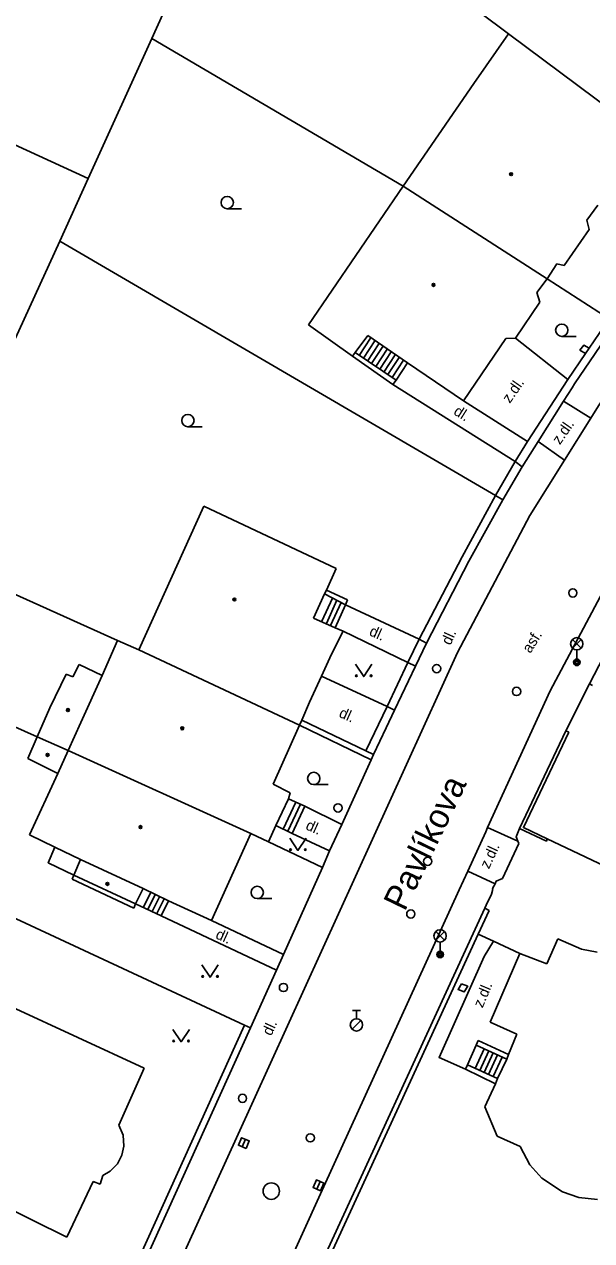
# Model space of a CAD drawing. Extents: x -600309 to -598967, y -1161267 to -1160292.
# Drawn here: x -599972.5 to -599938, y -1160562.7 to -1160488.8 of the extents above; entities that cross this region are included whole.
import ezdxf

# ---------------------------------------------------------------- set-up
doc = ezdxf.new("R2010")
doc.units = 0
for name, color, linetype in [('Level 10', 7, 'Continuous'), ('Level 11', 7, 'Continuous'), ('Level 24', 7, 'Continuous'), ('Level 27', 7, 'Continuous'), ('Level 28', 7, 'Continuous'), ('Level 31', 7, 'Continuous'), ('Level 33', 7, 'Continuous'), ('Level 36', 7, 'Continuous'), ('Level 39', 7, 'Continuous'), ('Level 40', 7, 'Continuous'), ('Level 5', 7, 'Continuous'), ('Level 50', 7, 'Continuous'), ('Level 51', 7, 'Continuous'), ('Level 7', 7, 'Continuous'), ('Level 8', 7, 'Continuous')]:
    doc.layers.add(name, color=color, linetype=linetype)

msp = doc.modelspace()

# ---------------------------------------------------------------- linework, layer by layer
at = {"layer": 'Level 10'}
for points in [[(-599935.03, -1160508.16), (-599937.49, -1160511.84), (-599937.56, -1160511.95), (-599938.03, -1160512.7), (-599939.64, -1160515.26), (-599941.75, -1160518.63), (-599946.15, -1160526.95), (-599959.57, -1160556.4699), (-599964.29, -1160566.81), (-599966.33, -1160571.27), (-599969.39, -1160577.98), (-599972.6, -1160585.01), (-599977.2, -1160595.1)], [(-599971.83, -1160598.12), (-599968.08, -1160589.86), (-599959.85, -1160571.72), (-599958.48, -1160568.71), (-599957.16, -1160565.81), (-599954.26, -1160559.42), (-599946.03, -1160541.39), (-599945.51, -1160540.25), (-599944.42, -1160537.85), (-599944.31, -1160537.6), (-599940.51, -1160529.28), (-599936.62, -1160521.9699), (-599931.52, -1160513.79)]]:
    msp.add_lwpolyline(points, dxfattribs=at)
at = {"layer": 'Level 11'}
for points in [[(-599951.42, -1160507.84), (-599952.11, -1160508.89)], [(-599951.17, -1160508.01), (-599951.86, -1160509.06)], [(-599950.92, -1160508.18), (-599951.61, -1160509.23)], [(-599950.67, -1160508.34), (-599951.36, -1160509.39)], [(-599942.62, -1160507.85), (-599939.43, -1160510.36)], [(-599952.53, -1160508.94), (-599950.07, -1160510.6599)], [(-599952.36, -1160508.7199), (-599949.87, -1160510.4)], [(-599950.42, -1160508.51), (-599951.11, -1160509.56)], [(-599950.17, -1160508.68), (-599950.86, -1160509.73)], [(-599949.93, -1160508.85), (-599950.62, -1160509.9)], [(-599949.68, -1160509.01), (-599950.37, -1160510.06)], [(-599949.43, -1160509.18), (-599950.12, -1160510.23)], [(-599949.87, -1160510.4), (-599949.18, -1160509.35)], [(-599950.07, -1160510.6599), (-599949.87, -1160510.4)], [(-599950.07, -1160510.6599), (-599942.63, -1160515.33)], [(-599941.88, -1160514.12), (-599945.78, -1160511.6599)], [(-599938.03, -1160512.7), (-599939.69, -1160511.68)], [(-599939.64, -1160515.26), (-599941.23, -1160514.13)], [(-599942.63, -1160515.33), (-599943.84, -1160517.4099)], [(-599952.82, -1160523.74), (-599954.1, -1160523.1599)], [(-599954.38, -1160525.04), (-599953.74, -1160523.64)], [(-599952.94, -1160524.05), (-599954.23, -1160523.39)], [(-599954.11, -1160525.18), (-599953.47, -1160523.78)], [(-599953.85, -1160525.31), (-599953.21, -1160523.91)], [(-599952.94, -1160524.05), (-599952.82, -1160523.74)], [(-599953.58, -1160525.45), (-599952.94, -1160524.05)], [(-599948.4699, -1160526.15), (-599952.94, -1160524.05)], [(-599949.15, -1160527.56), (-599953.1, -1160525.65)], [(-599948.4699, -1160526.15), (-599949.15, -1160527.56)], [(-599950.42, -1160530.23), (-599954.4, -1160528.39)], [(-599950.42, -1160530.23), (-599949.96, -1160530.45)], [(-599951.71, -1160532.93), (-599951.24, -1160533.16)], [(-599956.73, -1160537.7), (-599955.97, -1160536.05)], [(-599956.45, -1160537.82), (-599955.69, -1160536.17)], [(-599955.42, -1160536.3), (-599956.42, -1160535.84)], [(-599955.42, -1160536.3), (-599956.18, -1160537.95)], [(-599953.17, -1160537.4), (-599955.42, -1160536.3)], [(-599957.19, -1160537.48), (-599956.18, -1160537.95)], [(-599956.18, -1160537.95), (-599953.92, -1160539.02)], [(-599944.31, -1160537.6), (-599942.47, -1160538.43)], [(-599970.61, -1160538.79), (-599971.02, -1160539.74), (-599969.4699, -1160540.48)], [(-599965.7199, -1160542.23), (-599969.4699, -1160540.48)], [(-599943.86, -1160541.01), (-599945.51, -1160540.25)], [(-599965.23, -1160542.43), (-599964.79, -1160541.53)], [(-599964.96, -1160542.57), (-599964.52, -1160541.67)], [(-599965.7199, -1160542.23), (-599964.15, -1160542.96)], [(-599964.69, -1160542.7), (-599964.25, -1160541.8)], [(-599964.42, -1160542.83), (-599963.98, -1160541.93)], [(-599963.71, -1160542.06), (-599964.15, -1160542.96)], [(-599964.15, -1160542.96), (-599957.14, -1160546.26)], [(-599961.1, -1160543.25), (-599956.7199, -1160545.32)], [(-599945.65, -1160552.29), (-599947.26, -1160551.57), (-599944.52, -1160545.43), (-599943.96, -1160544.5)], [(-599943.96, -1160544.5), (-599944.88, -1160544.08)], [(-599942.35, -1160545.25), (-599943.96, -1160544.5)], [(-599945.01, -1160550.82), (-599944.89, -1160550.55)], [(-599944.89, -1160550.55), (-599943.05, -1160551.4)], [(-599945.53, -1160552.02), (-599945.01, -1160550.82)], [(-599944.51, -1160551.05), (-599945.06, -1160552.24)], [(-599943.15, -1160551.67), (-599945.01, -1160550.82)], [(-599944.24, -1160551.17), (-599944.79, -1160552.36)], [(-599943.97, -1160551.3), (-599944.52, -1160552.49)], [(-599945.65, -1160552.29), (-599945.53, -1160552.02)], [(-599945.53, -1160552.02), (-599943.7, -1160552.86)], [(-599943.7, -1160551.42), (-599944.25, -1160552.61)], [(-599943.42, -1160551.55), (-599943.97, -1160552.74)], [(-599945.65, -1160552.29), (-599943.83, -1160553.17)]]:
    msp.add_lwpolyline(points, dxfattribs=at)
at = {"layer": 'Level 24'}
for points in [[(-599938.35, -1160508.77), (-599938.7, -1160508.57), (-599938.47, -1160508.27), (-599938.13, -1160508.44)], [(-599945.89, -1160547.1), (-599946.1, -1160547.45), (-599945.73, -1160547.59), (-599945.52, -1160547.24), (-599945.89, -1160547.1)]]:
    msp.add_lwpolyline(points, dxfattribs=at)
at = {"layer": 'Level 27'}
for p, q in [((-599959.2265, -1160557.0106), (-599959.0335, -1160556.5494)), ((-599954.6922, -1160559.5781), (-599954.4878, -1160559.1219))]:
    msp.add_line(p, q, dxfattribs=at)
for points in [[(-599958.9958, -1160557.1071), (-599958.8029, -1160556.6458), (-599959.2642, -1160556.4529), (-599959.4571, -1160556.9142)], [(-599954.4641, -1160559.6804), (-599954.2596, -1160559.2241), (-599954.7159, -1160559.0196), (-599954.9204, -1160559.4759)]]:
    msp.add_lwpolyline(points, close=True, dxfattribs=at)
msp.add_circle((-599957.46, -1160559.7), 0.5, dxfattribs=at)
at = {"layer": 'Level 28'}
for p, q in [((-599952.53, -1160548.715), (-599952.03, -1160548.715)), ((-599952.28, -1160549.215), (-599952.28, -1160548.715)), ((-599952.538, -1160549.862), (-599952.008, -1160549.332))]:
    msp.add_line(p, q, dxfattribs=at)
for centre, radius in [((-599939.13, -1160523.33), 0.25), ((-599942.55, -1160529.32), 0.25), ((-599947.95, -1160539.65), 0.25), ((-599948.98, -1160542.85), 0.25), ((-599956.7199, -1160547.32), 0.25), ((-599952.28, -1160549.59), 0.375), ((-599955.09, -1160556.46), 0.25)]:
    msp.add_circle(centre, radius, dxfattribs=at)
at = {"layer": 'Level 31'}
for centre in [(-599947.41, -1160527.93), (-599953.4, -1160536.4), (-599959.21, -1160554.06)]:
    msp.add_circle(centre, 0.25, dxfattribs=at)
at = {"layer": 'Level 33'}
for p, q in [((-599939.155, -1160526.69), (-599938.625, -1160526.16)), ((-599939.155, -1160526.16), (-599938.625, -1160526.69)), ((-599938.89, -1160526.8), (-599938.89, -1160527.55)), ((-599947.465, -1160544.45), (-599946.935, -1160543.92)), ((-599947.465, -1160543.92), (-599946.935, -1160544.45)), ((-599947.2, -1160544.56), (-599947.2, -1160545.31))]:
    msp.add_line(p, q, dxfattribs=at)
for centre, radius in [((-599938.89, -1160526.425), 0.375), ((-599938.89, -1160527.55), 0.2), ((-599938.89, -1160527.55), 0.1445), ((-599938.89, -1160527.55), 0.0876), ((-599947.2, -1160544.185), 0.375), ((-599947.2, -1160545.31), 0.2), ((-599947.2, -1160545.31), 0.1445), ((-599947.2, -1160545.31), 0.0876)]:
    msp.add_circle(centre, radius, dxfattribs=at)
at = {"layer": 'Level 36'}
for p, q in [((-599960.14, -1160499.975), (-599959.265, -1160499.975)), ((-599939.8, -1160507.735), (-599938.925, -1160507.735)), ((-599962.53, -1160513.225), (-599961.655, -1160513.225)), ((-599954.88, -1160534.985), (-599954.005, -1160534.985)), ((-599958.31, -1160541.915), (-599957.435, -1160541.915))]:
    msp.add_line(p, q, dxfattribs=at)
for points in [[(-599952.34, -1160527.67), (-599951.84, -1160528.42), (-599951.34, -1160527.67)], [(-599956.34, -1160538.24), (-599955.84, -1160538.99), (-599955.34, -1160538.24)], [(-599961.68, -1160545.95), (-599961.18, -1160546.7), (-599960.68, -1160545.95)], [(-599963.44, -1160549.87), (-599962.94, -1160550.62), (-599962.44, -1160549.87)]]:
    msp.add_lwpolyline(points, dxfattribs=at)
for centre, radius in [((-599960.1401, -1160499.5999), 0.375), ((-599939.8001, -1160507.3599), 0.375), ((-599962.5301, -1160512.8499), 0.375), ((-599952.2902, -1160528.3698), 0.05), ((-599951.3908, -1160528.3698), 0.05), ((-599954.8801, -1160534.6099), 0.375), ((-599956.2902, -1160538.9398), 0.05), ((-599955.3908, -1160538.9398), 0.05), ((-599958.3101, -1160541.5399), 0.375), ((-599961.6302, -1160546.6498), 0.05), ((-599960.7308, -1160546.6498), 0.05), ((-599963.3902, -1160550.5698), 0.05), ((-599962.4908, -1160550.5698), 0.05)]:
    msp.add_circle(centre, radius, dxfattribs=at)
at = {"layer": 'Level 39'}
for centre, radius in [((-599942.88, -1160497.87), 0.09), ((-599942.88, -1160497.87), 0.0398), ((-599947.6, -1160504.6), 0.09), ((-599947.6, -1160504.6), 0.0398), ((-599959.7, -1160523.73), 0.09), ((-599959.7, -1160523.73), 0.0398), ((-599969.82, -1160530.45), 0.09), ((-599969.82, -1160530.45), 0.0398), ((-599962.87, -1160531.56), 0.09), ((-599962.87, -1160531.56), 0.0398), ((-599971.06, -1160533.18), 0.09), ((-599971.06, -1160533.18), 0.0398), ((-599965.4099, -1160537.57), 0.09), ((-599965.4099, -1160537.57), 0.0398), ((-599967.42, -1160541.02), 0.09), ((-599967.42, -1160541.02), 0.0398)]:
    msp.add_circle(centre, radius, dxfattribs=at)
at = {"layer": 'Level 5'}
for points in [[(-599945.14, -1160492.36), (-599943.04, -1160489.33)], [(-599943.04, -1160489.33), (-599934.62, -1160495.63)], [(-599949.45, -1160498.59), (-599945.14, -1160492.36)], [(-599955.2, -1160507.04), (-599949.45, -1160498.59)], [(-599940.69, -1160504.23), (-599949.45, -1160498.59)], [(-599937.61, -1160499.76), (-599938.27, -1160500.67)], [(-599938.27, -1160500.67), (-599938.14, -1160501.24)], [(-599938.14, -1160501.24), (-599939.65, -1160503.43)], [(-599940.1, -1160503.32), (-599940.69, -1160504.23)], [(-599939.65, -1160503.43), (-599940.1, -1160503.32)], [(-599940.69, -1160504.23), (-599941.31, -1160505.07)], [(-599941.31, -1160505.07), (-599941.14, -1160505.6599)], [(-599941.14, -1160505.6599), (-599942.62, -1160507.85)], [(-599952.53, -1160508.94), (-599955.2, -1160507.04)], [(-599951.6, -1160507.67), (-599952.36, -1160508.7199)], [(-599949.18, -1160509.35), (-599951.6, -1160507.67)], [(-599943.2, -1160507.87), (-599945.78, -1160511.6599)], [(-599942.62, -1160507.85), (-599943.2, -1160507.87)], [(-599952.36, -1160508.7199), (-599952.53, -1160508.94)], [(-599945.78, -1160511.6599), (-599949.18, -1160509.35)], [(-599965.52, -1160526.8), (-599961.55, -1160518.05)], [(-599961.55, -1160518.05), (-599953.52, -1160521.85)], [(-599953.52, -1160521.85), (-599954.1, -1160523.1599)], [(-599954.1, -1160523.1599), (-599954.23, -1160523.39)], [(-599954.23, -1160523.39), (-599954.9, -1160524.87)], [(-599954.9, -1160524.87), (-599953.58, -1160525.45)], [(-599953.1, -1160525.65), (-599953.79, -1160527.06)], [(-599953.58, -1160525.45), (-599953.1, -1160525.65)], [(-599967.73, -1160528.36), (-599966.8, -1160526.2199)], [(-599966.8, -1160526.2199), (-599965.52, -1160526.8)], [(-599965.52, -1160526.8), (-599955.75, -1160531.38)], [(-599953.79, -1160527.06), (-599954.4, -1160528.39), (-599955.13, -1160529.9699)], [(-599970.9099, -1160530.31), (-599969.93, -1160528.26)], [(-599969.93, -1160528.26), (-599969.52, -1160528.44)], [(-599969.52, -1160528.44), (-599969.14, -1160527.68)], [(-599969.14, -1160527.68), (-599967.73, -1160528.36)], [(-599969.04, -1160531.2), (-599967.73, -1160528.36)], [(-599971.7, -1160532.08), (-599970.9099, -1160530.31)], [(-599955.13, -1160529.9699), (-599955.61, -1160531.06)], [(-599969.81, -1160532.9099), (-599969.04, -1160531.2)], [(-599955.61, -1160531.06), (-599955.75, -1160531.38)], [(-599972.26, -1160533.39), (-599971.7, -1160532.08)], [(-599971.7, -1160532.08), (-599969.81, -1160532.9099)], [(-599955.75, -1160531.38), (-599957.35, -1160534.96)], [(-599970.44, -1160534.31), (-599972.26, -1160533.39)], [(-599970.44, -1160534.31), (-599969.81, -1160532.9099)], [(-599958.71, -1160537.96), (-599969.81, -1160532.9099)], [(-599972.15, -1160538.03), (-599970.44, -1160534.31)], [(-599957.35, -1160534.96), (-599956.31, -1160535.49)], [(-599956.31, -1160535.49), (-599956.42, -1160535.84)], [(-599956.42, -1160535.84), (-599957.19, -1160537.48)], [(-599958.71, -1160537.96), (-599961.1, -1160543.25)], [(-599957.63, -1160538.4699), (-599958.71, -1160537.96)], [(-599957.19, -1160537.48), (-599957.63, -1160538.4699)], [(-599970.61, -1160538.79), (-599972.15, -1160538.03)], [(-599969.06, -1160539.54), (-599970.61, -1160538.79)], [(-599969.4699, -1160540.48), (-599969.06, -1160539.54)], [(-599965.25, -1160541.31), (-599969.06, -1160539.54)], [(-599969.56, -1160540.74), (-599969.4699, -1160540.48)], [(-599965.81, -1160542.5), (-599969.56, -1160540.74)], [(-599965.25, -1160541.31), (-599965.7199, -1160542.23)], [(-599963.71, -1160542.06), (-599965.25, -1160541.31)], [(-599965.7199, -1160542.23), (-599965.81, -1160542.5)], [(-599961.1, -1160543.25), (-599963.71, -1160542.06)], [(-599940.7199, -1160545.88), (-599940.04, -1160544.36)], [(-599940.04, -1160544.36), (-599938.61, -1160544.98)], [(-599944.15, -1160549.42), (-599942.35, -1160545.25)], [(-599942.35, -1160545.25), (-599940.7199, -1160545.88)], [(-599938.61, -1160544.98), (-599937.65, -1160545.18)], [(-599977.31, -1160546.63), (-599965.19, -1160552.23)], [(-599942.54, -1160550.1599), (-599944.15, -1160549.42)], [(-599943.05, -1160551.4), (-599942.54, -1160550.1599)], [(-599943.7, -1160552.86), (-599943.15, -1160551.67)], [(-599943.15, -1160551.67), (-599943.05, -1160551.4)], [(-599965.19, -1160552.23), (-599966.73, -1160555.69)], [(-599944.4699, -1160554.57), (-599943.83, -1160553.17)], [(-599943.83, -1160553.17), (-599943.7, -1160552.86)], [(-599943.7199, -1160556.36), (-599944.4699, -1160554.57)], [(-599966.4699, -1160556.3), (-599966.73, -1160555.69)], [(-599966.42, -1160556.9699), (-599966.4699, -1160556.3)], [(-599942.34, -1160556.99), (-599943.7199, -1160556.36)], [(-599966.54, -1160557.51), (-599966.42, -1160556.9699)], [(-599941.74, -1160558.11), (-599942.34, -1160556.99)], [(-599966.81, -1160558.05), (-599966.54, -1160557.51)], [(-599967.69, -1160558.76), (-599967.25, -1160558.49)], [(-599967.25, -1160558.49), (-599966.81, -1160558.05)], [(-599941.01, -1160558.92), (-599941.74, -1160558.11)], [(-599968.28, -1160559.11), (-599969.89, -1160562.49)], [(-599967.86, -1160559.27), (-599968.28, -1160559.11)], [(-599967.69, -1160558.76), (-599967.86, -1160559.27)], [(-599939.76, -1160559.75), (-599941.01, -1160558.92)], [(-599938.76, -1160560.09), (-599939.76, -1160559.75)], [(-599937.63, -1160560.21), (-599938.76, -1160560.09)], [(-599969.89, -1160562.49), (-599974.13, -1160560.4099)]]:
    msp.add_lwpolyline(points, dxfattribs=at)
at = {"layer": 'Level 51'}
for points in [[(-599964.73, -1160489.62), (-599961.74, -1160483.02)], [(-599968.6, -1160498.13), (-599964.73, -1160489.62)], [(-599964.73, -1160489.62), (-599949.45, -1160498.59)], [(-599979.59, -1160493.09), (-599968.6, -1160498.13)], [(-599970.31, -1160501.94), (-599968.6, -1160498.13)], [(-599975.54, -1160513.33), (-599970.31, -1160501.94)], [(-599978.92, -1160520.78), (-599966.8, -1160526.2199)], [(-599981.94, -1160527.49), (-599971.7, -1160532.08)]]:
    msp.add_lwpolyline(points, dxfattribs=at)
at = {"layer": 'Level 7'}
for points in [[(-599950.1, -1160484.05), (-599943.04, -1160489.33)], [(-599970.31, -1160501.94), (-599943.84, -1160517.4099)], [(-599940.69, -1160504.23), (-599936.92, -1160506.67)], [(-599942.2, -1160515.67), (-599941.23, -1160514.13), (-599939.69, -1160511.68), (-599939.18, -1160510.86), (-599939.02, -1160510.61), (-599936.52, -1160506.92)], [(-599936.92, -1160506.67), (-599938.13, -1160508.44), (-599938.35, -1160508.77), (-599939.43, -1160510.36)], [(-599939.43, -1160510.36), (-599941.88, -1160514.12)], [(-599941.88, -1160514.12), (-599942.63, -1160515.33)], [(-599942.63, -1160515.33), (-599942.2, -1160515.67)], [(-599943.84, -1160517.4099), (-599945.86, -1160521.14), (-599948.4699, -1160526.15)], [(-599948.02, -1160526.38), (-599945.45, -1160521.4), (-599943.39, -1160517.67)], [(-599943.84, -1160517.4099), (-599943.39, -1160517.67)], [(-599935.25, -1160523.34), (-599938.12, -1160528.86), (-599937.94, -1160528.96)], [(-599948.02, -1160526.38), (-599948.4699, -1160526.15)], [(-599949.15, -1160527.56), (-599950.42, -1160530.23), (-599951.71, -1160532.93), (-599955.61, -1160531.06)], [(-599948.69, -1160527.78), (-599949.15, -1160527.56)], [(-599951.39, -1160533.48), (-599951.24, -1160533.16), (-599950.47, -1160531.53), (-599949.96, -1160530.45), (-599948.69, -1160527.78)], [(-599955.75, -1160531.38), (-599951.39, -1160533.48)], [(-599939.38, -1160531.8), (-599939.56, -1160531.71), (-599942.37, -1160537.65)], [(-599940.68, -1160538.28), (-599942.13, -1160537.6), (-599939.38, -1160531.8)], [(-599951.39, -1160533.48), (-599953.17, -1160537.4)], [(-599986.29, -1160536.95), (-599959.08, -1160549.61)], [(-599942.42, -1160538.57), (-599942.47, -1160538.43), (-599942.57, -1160538.16), (-599942.37, -1160537.65)], [(-599940.68, -1160538.28), (-599940.74, -1160538.42), (-599942.37, -1160537.65)], [(-599957.63, -1160538.4699), (-599954.35, -1160540.02)], [(-599925.94, -1160545.28), (-599940.68, -1160538.28)], [(-599953.92, -1160539.02), (-599954.35, -1160540.02)], [(-599954.35, -1160540.02), (-599956.7199, -1160545.32)], [(-599944.07, -1160541.64), (-599944, -1160541.35), (-599944.01, -1160541.31), (-599943.86, -1160541.01), (-599943.79, -1160540.86), (-599943.41, -1160540.69)], [(-599955.35, -1160566.84), (-599955.62, -1160566.71), (-599955.52, -1160566.49), (-599944.48, -1160542.5), (-599944.21, -1160542.63)], [(-599955.35, -1160566.84), (-599954.64, -1160565.3), (-599944.88, -1160544.08), (-599944.21, -1160542.63)], [(-599957.14, -1160546.26), (-599958.73, -1160549.78)], [(-599959.08, -1160549.61), (-599966.84, -1160566.75)], [(-599966.48, -1160566.91), (-599958.73, -1160549.78)], [(-599959.08, -1160549.61), (-599958.73, -1160549.78)]]:
    msp.add_lwpolyline(points, dxfattribs=at)
at = {"layer": 'Level 8'}
for points in [[(-599943.39, -1160517.67), (-599942.2, -1160515.67)], [(-599948.69, -1160527.78), (-599948.02, -1160526.38)], [(-599938.12, -1160528.86), (-599939.56, -1160531.71)], [(-599953.92, -1160539.02), (-599953.17, -1160537.4)], [(-599942.42, -1160538.57), (-599943.41, -1160540.69)], [(-599944.07, -1160541.64), (-599944.39, -1160542.31), (-599944.48, -1160542.5)], [(-599957.14, -1160546.26), (-599956.7199, -1160545.32)]]:
    msp.add_lwpolyline(points, dxfattribs=at)

# ---------------------------------------------------------------- texts
at = {"layer": 'Level 40'}
for s, height, rotation, p in [('z.dl.', 0.65, 55.155708, (-599942.96, -1160511.84)), ('dl.', 0.65, 327.757533, (-599946.43, -1160512.44)), ('z.dl.', 0.65, 55.155708, (-599939.92, -1160514.36)), ('dl.', 0.64999, 335.760336, (-599951.56, -1160525.88)), ('dl.', 0.65, 65.468942, (-599946.57, -1160526.55)), ('asf.', 0.65, 58.057619, (-599941.71, -1160527.04)), ('dl.', 0.64999, 335.760336, (-599953.4, -1160530.85)), ('dl.', 0.64999, 335.760336, (-599955.42, -1160537.68)), ('z.dl.', 0.65, 64.968314, (-599944.23, -1160540.15)), ('dl.', 0.64999, 335.760336, (-599960.9, -1160544.31)), ('z.dl.', 0.65, 67, (-599944.62, -1160548.6)), ('dl.', 0.65, 65.468942, (-599957.46, -1160550.3))]:
    msp.add_text(s, height=height, rotation=rotation, dxfattribs=at).set_placement(p)
at = {"layer": 'Level 50'}
msp.add_text('Pavlíkova', height=1.5, rotation=64.18045, dxfattribs=at).set_placement((-599949.3479, -1160542.7412))

doc.saveas('drawing.dxf')
